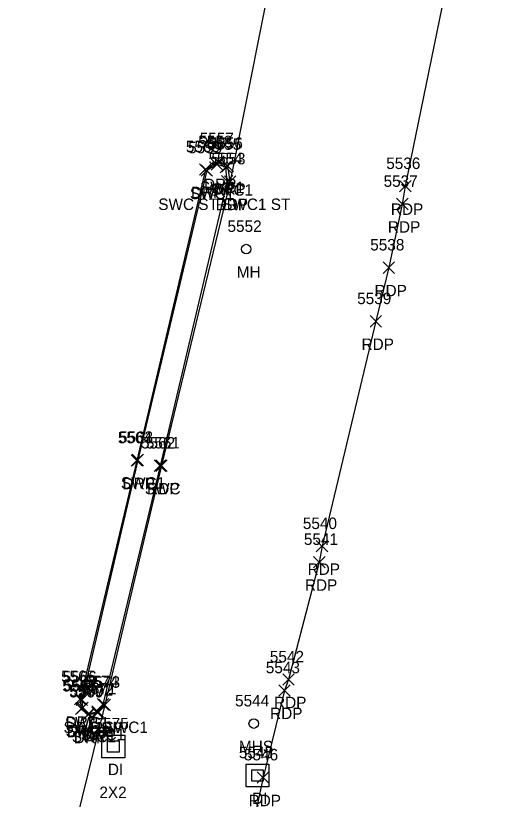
# Model space of a CAD drawing. Extents: x 1462668 to 1465147, y 550359 to 557351.
# Drawn here: x 1464308 to 1464390.6, y 553815.9 to 553952.7 of the extents above; entities that cross this region are included whole.
import ezdxf

# ---------------------------------------------------------------- set-up
doc = ezdxf.new("R2010")
doc.units = 0
for name, color, linetype in [('D_A', 7, 'Continuous'), ('D_C', 7, 'Continuous'), ('D_I', 7, 'Continuous'), ('DS', 7, 'Continuous'), ('P_A', 7, 'Continuous'), ('P_I', 7, 'Continuous'), ('P_TIC', 7, 'Continuous'), ('PET', 7, 'Continuous'), ('R_A', 7, 'Continuous'), ('R_I', 7, 'Continuous'), ('R_TIC', 7, 'Continuous'), ('RDP', 7, 'Continuous'), ('RSW', 7, 'Continuous'), ('U_A', 7, 'Continuous'), ('U_I', 7, 'Continuous'), ('USMH', 7, 'Continuous'), ('UUMH', 7, 'Continuous')]:
    doc.layers.add(name, color=color, linetype=linetype)

msp = doc.modelspace()

# ---------------------------------------------------------------- linework, layer by layer
at = {"layer": 'DS'}
for p, q in [((1464323.02, 553827.16), (1464327.02, 553827.16)), ((1464323.02, 553823.16), (1464323.02, 553827.16)), ((1464324.02, 553824.16), (1464324.02, 553826.16)), ((1464324.02, 553826.16), (1464326.02, 553826.16)), ((1464326.02, 553826.16), (1464326.02, 553824.16)), ((1464327.02, 553827.16), (1464327.02, 553823.16)), ((1464325.03, 553825.16), (1464325.03, 553825.16)), ((1464325.03, 553825.16), (1464325.03, 553825.16)), ((1464326.02, 553824.16), (1464324.02, 553824.16)), ((1464327.02, 553823.16), (1464323.02, 553823.16)), ((1464348.17, 553822.1), (1464352.17, 553822.1)), ((1464348.17, 553818.11), (1464348.17, 553822.1)), ((1464352.17, 553822.1), (1464352.17, 553818.11)), ((1464349.17, 553819.11), (1464349.17, 553821.11)), ((1464349.17, 553821.11), (1464351.17, 553821.11)), ((1464351.17, 553821.11), (1464351.17, 553819.11)), ((1464350.18, 553820.11), (1464350.18, 553820.11)), ((1464350.18, 553820.11), (1464350.18, 553820.11)), ((1464352.17, 553818.11), (1464348.17, 553818.11)), ((1464351.17, 553819.11), (1464349.17, 553819.11))]:
    msp.add_line(p, q, dxfattribs=at)
at = {"layer": 'P_TIC'}
for points in [[(1464344.39, 553922.73), (1464346.39, 553924.73)], [(1464346.39, 553922.73), (1464344.39, 553924.73)], [(1464374.94, 553921.91), (1464376.94, 553923.91)], [(1464376.94, 553921.91), (1464374.94, 553923.91)], [(1464374.42, 553918.8), (1464376.42, 553920.8)], [(1464376.42, 553918.8), (1464374.42, 553920.8)], [(1464372.08, 553907.7), (1464374.08, 553909.7)], [(1464374.08, 553907.7), (1464372.08, 553909.7)], [(1464369.82, 553898.34), (1464371.82, 553900.34)], [(1464371.82, 553898.34), (1464369.82, 553900.34)], [(1464332.43, 553873.16), (1464334.43, 553875.16)], [(1464334.43, 553873.16), (1464332.43, 553875.16)], [(1464360.43, 553859.1), (1464362.43, 553861.1)], [(1464362.43, 553859.1), (1464360.43, 553861.1)], [(1464359.95, 553856.33), (1464361.95, 553858.33)], [(1464361.95, 553856.33), (1464359.95, 553858.33)], [(1464354.58, 553835.84), (1464356.58, 553837.84)], [(1464356.58, 553835.84), (1464354.58, 553837.84)], [(1464353.88, 553833.94), (1464355.88, 553835.94)], [(1464355.88, 553833.94), (1464353.88, 553835.94)], [(1464322.52, 553831.4), (1464324.52, 553833.4)], [(1464324.52, 553831.4), (1464322.52, 553833.4)], [(1464350.13, 553818.74), (1464352.13, 553820.74)], [(1464352.13, 553818.74), (1464350.13, 553820.74)]]:
    msp.add_lwpolyline(points, dxfattribs=at)
at = {"layer": 'PET'}
for points in [[(1464359.48, 554043.27), (1464359.18, 554029.07), (1464357.96, 554009.1), (1464355, 553971.72), (1464354.56, 553966.43), (1464353.9, 553966.42), (1464345.39, 553923.73), (1464333.43, 553874.16), (1464323.52, 553832.4), (1464316.65, 553804.32), (1464311.56, 553777.78), (1464308, 553753.67)], [(1464390.6, 553996.13), (1464383.71, 553960.94), (1464375.94, 553922.91), (1464375.42, 553919.8), (1464373.08, 553908.7), (1464370.82, 553899.34), (1464361.43, 553860.1), (1464360.95, 553857.33), (1464355.58, 553836.84), (1464354.88, 553834.94), (1464351.13, 553819.74), (1464346.72, 553799.45)]]:
    msp.add_lwpolyline(points, dxfattribs=at)
at = {"layer": 'R_TIC'}
for points in [[(1464342.1, 553925.71), (1464344.1, 553927.71)], [(1464344.1, 553925.71), (1464342.1, 553927.71)], [(1464342.35, 553926.23), (1464344.35, 553928.23)], [(1464344.35, 553926.23), (1464342.35, 553928.23)], [(1464343.98, 553925.44), (1464345.98, 553927.44)], [(1464345.98, 553925.44), (1464343.98, 553927.44)], [(1464340.08, 553924.83), (1464342.08, 553926.83)], [(1464342.08, 553924.83), (1464340.08, 553926.83)], [(1464340.35, 553924.66), (1464342.35, 553926.66)], [(1464342.35, 553924.66), (1464340.35, 553926.66)], [(1464343.64, 553925.26), (1464345.64, 553927.26)], [(1464345.64, 553925.26), (1464343.64, 553927.26)], [(1464343.89, 553922.76), (1464345.89, 553924.76)], [(1464345.89, 553922.76), (1464343.89, 553924.76)], [(1464343.89, 553922.76), (1464345.89, 553924.76)], [(1464345.89, 553922.76), (1464343.89, 553924.76)], [(1464344.39, 553922.73), (1464346.39, 553924.73)], [(1464346.39, 553922.73), (1464344.39, 553924.73)], [(1464328.14, 553874.05), (1464330.14, 553876.05)], [(1464330.14, 553874.05), (1464328.14, 553876.05)], [(1464328.31, 553874.14), (1464330.31, 553876.14)], [(1464330.31, 553874.14), (1464328.31, 553876.14)], [(1464332.17, 553873.15), (1464334.17, 553875.15)], [(1464334.17, 553873.15), (1464332.17, 553875.15)], [(1464318.23, 553832.41), (1464320.23, 553834.41)], [(1464320.23, 553832.41), (1464318.23, 553834.41)], [(1464318.55, 553832.3), (1464320.55, 553834.3)], [(1464320.55, 553832.3), (1464318.55, 553834.3)], [(1464322.22, 553831.51), (1464324.22, 553833.51)], [(1464324.22, 553831.51), (1464322.22, 553833.51)], [(1464322.22, 553831.51), (1464324.22, 553833.51)], [(1464324.22, 553831.51), (1464322.22, 553833.51)], [(1464322.52, 553831.4), (1464324.52, 553833.4)], [(1464324.52, 553831.4), (1464322.52, 553833.4)], [(1464318.44, 553830.76), (1464320.44, 553832.76)], [(1464320.44, 553830.76), (1464318.44, 553832.76)], [(1464318.66, 553830.89), (1464320.66, 553832.89)], [(1464320.66, 553830.89), (1464318.66, 553832.89)], [(1464319.66, 553829.72), (1464321.66, 553831.72)], [(1464321.66, 553829.72), (1464319.66, 553831.72)], [(1464319.75, 553829.89), (1464321.75, 553831.89)], [(1464321.75, 553829.89), (1464319.75, 553831.89)], [(1464321.31, 553830.26), (1464323.31, 553832.26)], [(1464323.31, 553830.26), (1464321.31, 553832.26)], [(1464321.31, 553830.04), (1464323.31, 553832.04)], [(1464323.31, 553830.04), (1464321.31, 553832.04)]]:
    msp.add_lwpolyline(points, dxfattribs=at)
at = {"layer": 'RDP'}
msp.add_lwpolyline([(1464345.39, 553923.73), (1464344.98, 553926.44), (1464343.35, 553927.23), (1464341.08, 553925.83), (1464329.14, 553875.05), (1464319.23, 553833.41), (1464319.44, 553831.76), (1464320.66, 553830.72), (1464322.31, 553831.04), (1464323.52, 553832.4)], dxfattribs=at)
at = {"layer": 'RSW'}
for points in [[(1464344.89, 553923.76), (1464344.64, 553926.26), (1464343.1, 553926.71), (1464341.35, 553925.66), (1464329.31, 553875.14), (1464319.55, 553833.3), (1464319.66, 553831.89), (1464320.75, 553830.89), (1464322.31, 553831.26), (1464323.22, 553832.51)], [(1464344.89, 553923.76), (1464333.17, 553874.15), (1464323.22, 553832.51)]]:
    msp.add_lwpolyline(points, dxfattribs=at)
at = {"layer": 'USMH'}
for p, q in [((1464349.52, 553829.16), (1464349.52, 553829.16)), ((1464350.35, 553829.16), (1464350.35, 553829.16))]:
    msp.add_line(p, q, dxfattribs=at)
msp.add_circle((1464349.52, 553829.16), 0.833, dxfattribs=at)
at = {"layer": 'UUMH'}
for p, q in [((1464348.2, 553911.94), (1464348.2, 553911.94)), ((1464349.03, 553911.94), (1464349.03, 553911.94))]:
    msp.add_line(p, q, dxfattribs=at)
msp.add_circle((1464348.2, 553911.94), 0.833, dxfattribs=at)

# ---------------------------------------------------------------- texts
at = {"layer": 'D_A'}
for p in [(1464324.08, 553820.16), (1464349.23, 553815.11)]:
    msp.add_text('DI', height=2, dxfattribs=at).set_placement(p)
at = {"layer": 'D_C'}
msp.add_text('2X2', height=2, dxfattribs=at).set_placement((1464322.6, 553816.16))
at = {"layer": 'D_I'}
for s, p in [('5575', (1464321.77, 553828.16)), ('5545', (1464346.92, 553823.11))]:
    msp.add_text(s, height=2, dxfattribs=at).set_placement(p)
at = {"layer": 'P_A'}
for p in [(1464342.88, 553918.73), (1464373.43, 553917.91), (1464372.91, 553914.8), (1464370.57, 553903.7), (1464368.31, 553894.34), (1464330.92, 553869.16), (1464358.91, 553855.1), (1464358.44, 553852.33), (1464353.06, 553831.84), (1464352.37, 553829.94), (1464321.01, 553827.4), (1464348.62, 553814.74)]:
    msp.add_text('RDP', height=2, dxfattribs=at).set_placement(p)
at = {"layer": 'P_I'}
for s, p in [('5553', (1464342.13, 553926.73)), ('5536', (1464372.62, 553925.91)), ('5537', (1464372.16, 553922.8)), ('5538', (1464369.83, 553911.7)), ('5539', (1464367.55, 553902.34)), ('5561', (1464330.69, 553877.16)), ('5540', (1464358.08, 553863.1)), ('5541', (1464358.26, 553860.33)), ('5542', (1464352.32, 553839.84)), ('5543', (1464351.62, 553837.94)), ('5573', (1464320.26, 553835.4)), ('5546', (1464347.82, 553822.74))]:
    msp.add_text(s, height=2, dxfattribs=at).set_placement(p)
at = {"layer": 'R_A'}
for s, p in [('SWC1', (1464340.14, 553921.71)), ('DRP', (1464340.84, 553922.23)), ('SWC1', (1464341.68, 553921.26)), ('DRP', (1464342.47, 553921.44)), ('SWC1', (1464338.39, 553920.66)), ('DRP', (1464338.56, 553920.83)), ('SWC ST SWC1 ST', (1464332.87, 553918.76)), ('SWC ST SWC1 ST', (1464332.87, 553918.76)), ('DRP', (1464342.88, 553918.73)), ('SWC1', (1464326.35, 553870.14)), ('DRP', (1464326.63, 553870.05)), ('SWC', (1464330.53, 553869.15)), ('SWC1', (1464316.59, 553828.3)), ('DRP', (1464316.72, 553828.41)), ('SWC SWC1', (1464316.35, 553827.51)), ('SWC SWC1', (1464316.35, 553827.51)), ('SWC1', (1464316.7, 553826.89)), ('DRP', (1464321.01, 553827.4)), ('DRP', (1464316.93, 553826.76)), ('SWC1', (1464317.79, 553825.89)), ('DRP', (1464318.15, 553825.72)), ('SWC1', (1464319.35, 553826.26)), ('DRP', (1464319.8, 553826.04))]:
    msp.add_text(s, height=2, dxfattribs=at).set_placement(p)
at = {"layer": 'R_I'}
for s, p in [('5558', (1464339.84, 553929.71)), ('5557', (1464340.09, 553930.23)), ('5556', (1464341.67, 553929.44)), ('5560', (1464337.68, 553928.83)), ('5559', (1464338.08, 553928.66)), ('5555', (1464341.38, 553929.26)), ('5554', (1464341.63, 553926.76)), ('5554', (1464341.63, 553926.76)), ('5553', (1464342.13, 553926.73)), ('5564', (1464325.83, 553878.05)), ('5563', (1464326.01, 553878.14)), ('5562', (1464329.86, 553877.15)), ('5565', (1464315.92, 553836.41)), ('5566', (1464316.19, 553836.3)), ('5574', (1464319.96, 553835.51)), ('5574', (1464319.96, 553835.51)), ('5573', (1464320.26, 553835.4)), ('5568', (1464316.13, 553834.76)), ('5567', (1464316.36, 553834.89)), ('5569', (1464317.34, 553833.72)), ('5570', (1464317.4, 553833.89)), ('5572', (1464319.05, 553834.04)), ('5571', (1464319.61, 553834.26))]:
    msp.add_text(s, height=2, dxfattribs=at).set_placement(p)
at = {"layer": 'U_A'}
for s, p in [('MH', (1464346.56, 553906.94)), ('MHS', (1464346.94, 553824.16))]:
    msp.add_text(s, height=2, dxfattribs=at).set_placement(p)
at = {"layer": 'U_I'}
for s, p in [('5552', (1464344.94, 553914.94)), ('5544', (1464346.26, 553832.16))]:
    msp.add_text(s, height=2, dxfattribs=at).set_placement(p)

doc.saveas('drawing.dxf')
